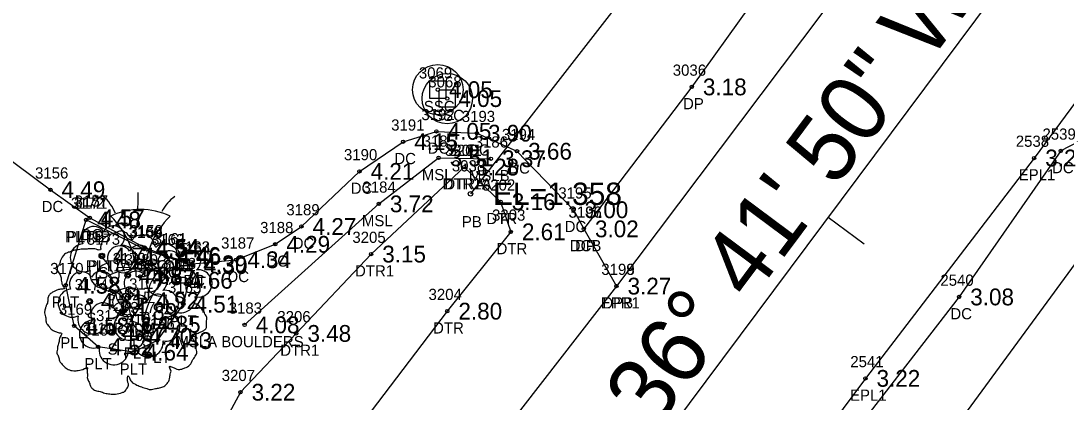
# Model space of a CAD drawing. Extents: x 2608598 to 2610682, y 641451 to 643526.
# Drawn here: x 2609967.6 to 2610061, y 642037.2 to 642071.3 of the extents above; entities that cross this region are included whole.
import ezdxf

# ---------------------------------------------------------------- set-up
doc = ezdxf.new("R2010")
doc.units = 0
for name, color, linetype in [('RD_EX_BldgApp', 7, 'Continuous'), ('RD_EX_BldgApp_txCode', 7, 'Continuous'), ('RD_EX_Conc', 7, 'Continuous'), ('RD_EX_Conc_txCode', 7, 'Continuous'), ('RD_EX_DR_Pipe', 7, 'Continuous'), ('RD_EX_DR_Pipe_txCode', 7, 'Continuous'), ('RD_EX_Driveway', 7, 'Continuous'), ('RD_EX_Driveway_txCode', 7, 'Continuous'), ('RD_EX_H2O', 7, 'Continuous'), ('RD_EX_H2O_txCode', 7, 'Continuous'), ('RD_EX_Misc', 7, 'Continuous'), ('RD_EX_Misc_txCode', 7, 'Continuous'), ('RD_EX_Road', 7, 'Continuous'), ('RD_EX_Road_txCode', 7, 'Continuous'), ('RD_EX_TX_BldgApp_ELEV', 7, 'Continuous'), ('RD_EX_TX_Conc_ELEV', 7, 'Continuous'), ('RD_EX_TX_Driveway_ELEV', 7, 'Continuous'), ('RD_EX_TX_H2O_ELEV', 7, 'Continuous'), ('RD_EX_TX_Misc_ELEV', 7, 'Continuous'), ('RD_EX_TX_Road_ELEV', 7, 'Continuous'), ('RD_EX_TX_UT_ELEV', 7, 'Continuous'), ('RD_EX_TX_VEG_ELEV', 7, 'Continuous'), ('RD_EX_UT', 7, 'Continuous'), ('RD_EX_UT_txCode', 7, 'Continuous'), ('RD_EX_VEG', 7, 'Continuous'), ('RD_EX_VEG_txCode', 7, 'Continuous'), ('RD_HC_Cl', 7, 'Continuous'), ('RD_HC_Data', 7, 'Continuous'), ('RD_HC_Data_Tic', 7, 'Continuous'), ('RD_SMD_Locator', 7, 'Continuous'), ('RD_TX_Pipe_ElevEX', 7, 'Continuous')]:
    doc.layers.add(name, color=color, linetype=linetype)

msp = doc.modelspace()

# ---------------------------------------------------------------- linework, layer by layer
at = {"layer": 'RD_EX_BldgApp'}
for p, q in [((2609978.641, 642050.937), (2609973.438, 642053.541)), ((2609977.922, 642048.486), (2609978.672, 642048.486)), ((2609977.679, 642043.16), (2609978.429, 642043.16))]:
    msp.add_line(p, q, dxfattribs=at)
msp.add_lwpolyline([(2609978.641, 642050.937), (2609980.61, 642050.282), (2609982.959, 642049.455), (2609982.128, 642046.005), (2609979.78, 642042.749), (2609977.686, 642041.715), (2609974.532, 642042.189), (2609972.382, 642044.057), (2609971.623, 642047.695), (2609973.438, 642053.541)], dxfattribs=at)
for centre, radius, start, end in [((2609971.605, 642052.128), 4.895, 24.32791, 46.26654), ((2609940.216, 642055.824), 37.876, 358.06712, 0.27154), ((2609983.185, 642052.879), 3.283, 123.29064, 154.48862), ((2609978.297, 642048.486), 5.997, 63.77943, 116.22057), ((2609970.422, 642048.486), 7.5, 0, 45.83662), ((2609986.172, 642048.486), 7.5, 134.16338, 180), ((2609971.361, 642046.803), 4.895, 24.32791, 46.26654), ((2609939.972, 642050.498), 37.876, 358.06712, 0.27154), ((2609982.942, 642047.553), 3.283, 123.29064, 154.48862), ((2609978.054, 642043.16), 5.997, 63.77943, 116.22057), ((2609970.179, 642043.16), 7.5, 0, 45.83662), ((2609985.929, 642043.16), 7.5, 134.16338, 180)]:
    msp.add_arc(centre, radius, start, end, dxfattribs=at)
at = {"layer": 'RD_EX_Conc'}
for points in [[(2609961.016, 642063.114), (2609970.253, 642056.24), (2609973.77, 642053.725), (2609978.671, 642051.077), (2609980.569, 642050.362), (2609982.905, 642049.619), (2609986.846, 642049.978), (2609990.334, 642051.359), (2609992.677, 642052.953), (2609997.86, 642057.875), (2610001.755, 642060.528), (2610004.736, 642061.459), (2610008.347, 642061.293), (2610011.93, 642059.679), (2610016.967, 642054.45), (2610017.895, 642052.738)], [(2610062.865, 642060.944), (2610060.494, 642059.714), (2610051.415, 642046.652), (2610037.455, 642028.596), (2610032.589, 642022.148), (2610033.33, 642021.486)]]:
    msp.add_lwpolyline(points, dxfattribs=at)
at = {"layer": 'RD_EX_DR_Pipe'}
for p, q in [((2610033.217, 642088.618), (2610007.781, 642055.878)), ((2610073.519, 642065.711), (2609997.656, 641962.025))]:
    msp.add_line(p, q, dxfattribs=at)
at = {"layer": 'RD_EX_Driveway'}
msp.add_lwpolyline([(2610042.94, 642077.419), (2610037.979, 642080.001), (2610027.537, 642065.432), (2610017.895, 642052.738), (2610020.807, 642047.622)], dxfattribs=at)
at = {"layer": 'RD_EX_H2O'}
for points in [[(2610007.204, 642058.263), (2609998.896, 642050.485), (2609992.217, 642043.39), (2609987.228, 642038.134), (2609984.424, 642032.942), (2609982.751, 642025.12), (2609982.447, 642024.16), (2609981.196, 642022.387), (2609981.259, 642019.853), (2609982.724, 642019.295), (2609985.043, 642018.208), (2609987.753, 642019.505)], [(2610007.204, 642058.263), (2610010.468, 642055.164), (2610011.37, 642052.471), (2610005.7, 642045.381), (2609992.131, 642027.498), (2609987.753, 642019.505)]]:
    msp.add_lwpolyline(points, dxfattribs=at)
at = {"layer": 'RD_EX_Misc'}
msp.add_lwpolyline([(2609987.6, 642044.154), (2609999.579, 642054.974), (2610004.928, 642059.092), (2610009.602, 642059.01)], dxfattribs=at)
at = {"layer": 'RD_EX_Road'}
for points in [[(2610073.957, 642143.053), (2610073.967, 642133.893), (2610072.62, 642129.267), (2610072.125, 642123.733), (2610071.192, 642117.593), (2610042.94, 642077.419), (2610042.982, 642077.082), (2610020.807, 642047.622), (2610010.682, 642034.572), (2609995.36, 642013.506), (2609993.975, 642012.164), (2609992.649, 642010.593), (2609982.727, 641996.329), (2609971.725, 641982.02), (2609971.56, 641981.898), (2609965.999, 641974.618)], [(2610116.512, 642103.007), (2610109.419, 642106.335), (2610102.937, 642107.104), (2610095.974, 642105.732), (2610091.028, 642103.088), (2610067.446, 642071.713), (2610058.11, 642059.075), (2610043.044, 642039.371), (2610035.942, 642029.795), (2610030.832, 642022.851), (2609999.348, 641980.077), (2609984.87, 641960.622)]]:
    msp.add_lwpolyline(points, dxfattribs=at)
at = {"layer": 'RD_EX_UT'}
for p, q in [((2610005.61, 642065.935), (2610004.11, 642065.935)), ((2610004.11, 642065.935), (2610004.11, 642064.435)), ((2610005.61, 642064.435), (2610005.61, 642065.935)), ((2610006.449, 642065.138), (2610004.949, 642065.138)), ((2610004.949, 642065.138), (2610004.949, 642063.638)), ((2610006.449, 642063.638), (2610006.449, 642065.138)), ((2610004.11, 642064.435), (2610005.61, 642064.435)), ((2610004.949, 642063.638), (2610006.449, 642063.638))]:
    msp.add_line(p, q, dxfattribs=at)
for centre in [(2610004.86, 642065.185), (2610005.699, 642064.388)]:
    msp.add_circle(centre, 2.25, dxfattribs=at)
at = {"layer": 'RD_EX_VEG'}
for centre, radius in [((2609974.848, 642050.317), 0.25), ((2609977.162, 642048.587), 0.25), ((2609981.64, 642048.142), 0.25), ((2609973.771, 642046.254), 0.25), ((2609978.635, 642046.316), 0.25), ((2609976.68, 642045.355), 0.25), ((2609976.668, 642045.336), 0.0001), ((2609978.765, 642044.205), 0.25), ((2609975.675, 642043.494), 0.25)]:
    msp.add_circle(centre, radius, dxfattribs=at)
for centre, radius, start, end in [((2609974.127, 642051.864), 1.084, 34.97629, 204.75602), ((2609975.893, 642052.019), 0.995, 308.76261, 152.04674), ((2609973.284, 642050.162), 1.257, 96.45179, 294.73401), ((2609976.44, 642050.134), 1.084, 34.97629, 204.75602), ((2609976.687, 642050.038), 1.218, 256.56668, 98.10463), ((2609978.207, 642050.289), 0.995, 308.76261, 152.04674), ((2609980.919, 642049.69), 1.084, 34.97629, 204.75602), ((2609982.685, 642049.844), 0.995, 308.76261, 152.04674), ((2609973.05, 642047.801), 1.084, 34.97629, 204.75602), ((2609975.093, 642048.721), 1.318, 166.88266, 5.75893), ((2609974.816, 642047.956), 0.995, 308.76261, 152.04674), ((2609975.598, 642048.431), 1.257, 96.45179, 294.73401), ((2609977.914, 642047.863), 1.084, 34.97629, 204.75602), ((2609979.001, 642048.307), 1.218, 256.56668, 98.10463), ((2609979.68, 642048.018), 0.995, 308.76261, 152.04674), ((2609980.076, 642047.987), 1.257, 96.45179, 294.73401), ((2609983.48, 642047.863), 1.218, 256.56668, 98.10463), ((2609972.207, 642046.098), 1.257, 96.45179, 294.73401), ((2609975.611, 642045.974), 1.218, 256.56668, 98.10463), ((2609977.071, 642046.161), 1.257, 96.45179, 294.73401), ((2609977.407, 642046.99), 1.318, 166.88266, 5.75893), ((2609980.474, 642046.037), 1.218, 256.56668, 98.10463), ((2609974.954, 642045.041), 1.084, 34.97629, 204.75602), ((2609976.72, 642045.196), 0.995, 308.76261, 152.04674), ((2609978.044, 642045.752), 1.084, 34.97629, 204.75602), ((2609979.81, 642045.907), 0.995, 308.76261, 152.04674), ((2609981.886, 642046.546), 1.318, 166.88266, 5.75893), ((2609977.201, 642044.049), 1.257, 96.45179, 294.73401), ((2609980.604, 642043.926), 1.218, 256.56668, 98.10463), ((2609974.017, 642044.657), 1.318, 166.88266, 5.75893), ((2609974.111, 642043.338), 1.257, 96.45179, 294.73401), ((2609977.514, 642043.215), 1.218, 256.56668, 98.10463), ((2609978.88, 642044.72), 1.318, 166.88266, 5.75893), ((2609979.01, 642042.609), 1.318, 166.88266, 5.75893), ((2609975.92, 642041.898), 1.318, 166.88266, 5.75893)]:
    msp.add_arc(centre, radius, start, end, dxfattribs=at)
for points in [[(2609976.812, 642052.522), (2609976.512, 642052.547), (2609976.188, 642052.447), (2609975.938, 642052.347), (2609975.713, 642052.272), (2609975.488, 642052.172), (2609975.188, 642051.997), (2609974.963, 642051.797), (2609974.838, 642051.547), (2609974.788, 642051.323), (2609974.738, 642051.048), (2609974.738, 642050.873), (2609974.613, 642050.848), (2609974.463, 642050.873), (2609974.213, 642050.948), (2609973.963, 642050.948), (2609973.714, 642050.948), (2609973.364, 642050.923), (2609973.014, 642050.923), (2609972.739, 642050.873), (2609972.414, 642050.823), (2609972.039, 642050.698), (2609971.689, 642050.573), (2609971.39, 642050.323), (2609971.14, 642049.848), (2609971.015, 642049.498), (2609970.865, 642049.248), (2609971.015, 642048.799), (2609971.19, 642048.449), (2609971.215, 642048.249), (2609971.29, 642047.824), (2609971.39, 642047.599), (2609971.515, 642047.399), (2609971.44, 642047.374), (2609971.065, 642047.324), (2609970.765, 642047.224), (2609970.34, 642046.999), (2609970.115, 642046.775), (2609970.015, 642046.45), (2609969.99, 642046.1), (2609969.89, 642045.9), (2609969.815, 642045.625), (2609969.79, 642045.55), (2609969.74, 642045.225), (2609969.84, 642044.775), (2609969.865, 642044.426), (2609969.99, 642044.201), (2609970.14, 642044.026), (2609970.315, 642043.776), (2609970.715, 642043.551), (2609971.04, 642043.451), (2609971.24, 642043.426), (2609971.065, 642042.926), (2609971.015, 642042.576), (2609970.89, 642042.177), (2609970.89, 642042.102), (2609970.84, 642041.627), (2609970.99, 642041.302), (2609971.065, 642040.927), (2609971.24, 642040.702), (2609971.515, 642040.402), (2609971.839, 642040.177), (2609972.339, 642040.052), (2609972.739, 642040.077), (2609973.314, 642040.252), (2609973.564, 642040.327), (2609973.539, 642040.152), (2609973.564, 642039.778), (2609973.564, 642039.353), (2609973.714, 642039.028), (2609973.814, 642038.753), (2609973.963, 642038.503), (2609974.288, 642038.278), (2609974.688, 642038.203), (2609975.113, 642038.053), (2609975.563, 642037.978), (2609976.063, 642037.953), (2609976.662, 642038.103), (2609976.937, 642038.228), (2609977.037, 642038.403), (2609977.237, 642038.778), (2609977.187, 642039.003), (2609977.212, 642039.603), (2609977.312, 642039.428), (2609977.487, 642039.078), (2609977.987, 642038.778), (2609978.387, 642038.603), (2609978.861, 642038.453), (2609979.161, 642038.378), (2609979.636, 642038.453), (2609980.011, 642038.528), (2609980.386, 642038.653), (2609980.686, 642038.928), (2609980.86, 642039.203), (2609980.91, 642039.478), (2609980.985, 642039.853), (2609981.035, 642040.027)], [(2609981.035, 642040.027), (2609980.96, 642040.202), (2609980.91, 642040.452), (2609980.985, 642040.427), (2609981.16, 642040.377), (2609981.435, 642040.252), (2609981.66, 642040.177), (2609981.985, 642040.202), (2609982.26, 642040.302), (2609982.71, 642040.577), (2609982.985, 642041.052), (2609983.259, 642041.452), (2609983.334, 642041.777), (2609983.284, 642042.002), (2609983.259, 642042.501), (2609983.059, 642042.751), (2609983.009, 642042.876), (2609982.91, 642043.276), (2609982.985, 642043.326), (2609983.259, 642043.376), (2609983.634, 642043.501), (2609983.909, 642043.626), (2609984.134, 642043.801), (2609984.209, 642044.026), (2609984.184, 642044.426), (2609984.234, 642044.825), (2609984.159, 642044.975), (2609984.059, 642045.125), (2609983.984, 642045.325), (2609983.834, 642045.475), (2609983.734, 642045.625), (2609983.634, 642045.725), (2609983.509, 642045.875), (2609983.334, 642046), (2609983.184, 642046.05), (2609983.134, 642046.2), (2609983.284, 642046.4), (2609983.334, 642046.5), (2609983.359, 642046.725), (2609983.584, 642047.074), (2609983.634, 642047.474), (2609983.584, 642047.899), (2609983.534, 642048.174), (2609983.384, 642048.449), (2609983.184, 642048.699), (2609983.059, 642048.874), (2609982.885, 642048.999), (2609982.56, 642049.124), (2609982.31, 642049.173), (2609981.96, 642049.173), (2609981.76, 642049.223), (2609981.785, 642049.273), (2609981.785, 642049.423), (2609981.785, 642049.698), (2609981.71, 642050.148), (2609981.56, 642050.648), (2609981.56, 642050.673), (2609981.46, 642050.923), (2609981.235, 642051.123), (2609981.06, 642051.223), (2609980.86, 642051.348), (2609980.611, 642051.373), (2609980.311, 642051.373), (2609980.036, 642051.323), (2609979.836, 642051.223), (2609979.661, 642051.098), (2609979.586, 642051.248), (2609979.486, 642051.547), (2609979.436, 642051.697), (2609979.286, 642051.872), (2609979.061, 642052.072), (2609978.611, 642052.197), (2609977.987, 642052.122), (2609977.687, 642051.922), (2609977.537, 642051.747), (2609977.487, 642051.872), (2609977.287, 642052.072), (2609977.187, 642052.247), (2609977.012, 642052.372), (2609976.862, 642052.472), (2609976.762, 642052.522)]]:
    msp.add_spline(points, degree=3, dxfattribs=at)
at = {"layer": 'RD_HC_Cl'}
msp.add_line((2610099.475, 642133.968), (2609975.324, 641967.39), dxfattribs=at)
at = {"layer": 'RD_HC_Data_Tic'}
msp.add_line((2610039.716, 642053.788), (2610042.924, 642051.398), dxfattribs=at)
at = {"layer": 'RD_SMD_Locator'}
for centre, radius in [((2610004.86, 642065.185), 0.15), ((2610027.537, 642065.432), 0.15), ((2610005.699, 642064.388), 0.15), ((2610004.736, 642061.459), 0.15), ((2610008.347, 642061.293), 0.15), ((2610001.755, 642060.528), 0.15), ((2610004.928, 642059.092), 0.15), ((2610009.602, 642059.01), 0.15), ((2610011.93, 642059.679), 0.15), ((2610058.11, 642059.075), 0.15), ((2610060.494, 642059.714), 0.15), ((2610007.204, 642058.263), 0.15), ((2610007.204, 642058.263), 0.15), ((2609997.86, 642057.875), 0.15), ((2609970.253, 642056.24), 0.15), ((2610007.781, 642055.878), 0.2), ((2609999.579, 642054.974), 0.15), ((2610010.468, 642055.164), 0.15), ((2610016.967, 642054.45), 0.15), ((2609973.438, 642053.541), 0.15), ((2609973.438, 642053.541), 0.15), ((2609973.77, 642053.725), 0.15), ((2609992.677, 642052.953), 0.15), ((2610011.37, 642052.471), 0.15), ((2610017.895, 642052.738), 0.15), ((2610017.895, 642052.738), 0.15), ((2609978.641, 642050.937), 0.15), ((2609978.641, 642050.937), 0.15), ((2609978.671, 642051.077), 0.15), ((2609990.334, 642051.359), 0.15), ((2609974.848, 642050.317), 0.15), ((2609980.569, 642050.362), 0.15), ((2609980.61, 642050.282), 0.15), ((2609986.846, 642049.978), 0.15), ((2609998.896, 642050.485), 0.15), ((2609982.905, 642049.619), 0.15), ((2609982.959, 642049.455), 0.15), ((2609977.162, 642048.587), 0.15), ((2609978.269, 642048.468), 0.15), ((2609981.64, 642048.142), 0.15), ((2609971.623, 642047.695), 0.15), ((2610020.807, 642047.622), 0.15), ((2610020.807, 642047.622), 0.15), ((2609973.771, 642046.254), 0.15), ((2609978.635, 642046.316), 0.15), ((2609982.128, 642046.005), 0.15), ((2610051.415, 642046.652), 0.15), ((2609976.68, 642045.355), 0.15), ((2610005.7, 642045.381), 0.15), ((2609972.382, 642044.057), 0.15), ((2609978.765, 642044.205), 0.15), ((2609987.6, 642044.154), 0.15), ((2609975.675, 642043.494), 0.15), ((2609978.026, 642043.142), 0.15), ((2609992.217, 642043.39), 0.15), ((2609974.532, 642042.189), 0.15), ((2609979.78, 642042.749), 0.15), ((2609977.686, 642041.715), 0.15), ((2610043.044, 642039.371), 0.15), ((2609987.228, 642038.134), 0.15)]:
    msp.add_circle(centre, radius, dxfattribs=at)

# ---------------------------------------------------------------- texts
at = {"layer": 'RD_EX_BldgApp_txCode'}
for s, p in [('3172', (2609972.091, 642054.541)), ('3171', (2609972.375, 642054.541)), ('3160', (2609977.231, 642051.937)), ('3159', (2609977.294, 642051.937)), ('PLT1B', (2609971.556, 642051.541)), ('PLTB', (2609971.721, 642051.541)), ('3162', (2609979.24, 642051.282)), ('3164', (2609981.589, 642050.455)), ('PLT1A 4STONE', (2609973.416, 642048.937)), ('PLTA 4STONE', (2609973.582, 642048.937)), ('3180', (2609976.883, 642049.468)), ('3170', (2609970.237, 642048.695)), ('PLT', (2609979.366, 642048.282)), ('3165', (2609980.757, 642047.005)), ('PLT', (2609981.715, 642047.455)), ('FLT', (2609977.049, 642046.468)), ('PLT', (2609970.379, 642045.695)), ('3169', (2609971.012, 642045.057)), ('3181', (2609976.963, 642044.142)), ('3166', (2609978.387, 642043.749)), ('PLT', (2609980.883, 642044.005)), ('3168', (2609973.162, 642043.189)), ('3167', (2609976.315, 642042.715)), ('PLT', (2609971.138, 642042.057)), ('FLT', (2609976.806, 642041.142)), ('PLT', (2609978.536, 642040.749)), ('PLT', (2609973.288, 642040.189)), ('PLT', (2609976.441, 642039.715))]:
    msp.add_text(s, height=1, dxfattribs=at).set_placement(p)
at = {"layer": 'RD_EX_Conc_txCode'}
for s, p in [('3192', (2610003.39, 642062.459)), ('3193', (2610007.001, 642062.293)), ('3191', (2610000.692, 642061.528)), ('3194', (2610010.583, 642060.679)), ('2539', (2610058.864, 642060.714)), ('DC', (2610003.957, 642059.459)), ('DC', (2610007.568, 642059.293)), ('3190', (2609996.474, 642058.875)), ('DC', (2610000.976, 642058.528)), ('3156', (2609968.883, 642057.24)), ('DC', (2610011.15, 642057.679)), ('DC', (2610059.715, 642057.714)), ('DC', (2609997.081, 642055.875)), ('3195', (2610015.62, 642055.45)), ('3157', (2609972.424, 642054.725)), ('DC', (2609969.473, 642054.24)), ('3189', (2609991.331, 642053.953)), ('3196', (2610016.525, 642053.738)), ('DC', (2609972.99, 642051.725)), ('3158', (2609977.324, 642052.077)), ('3188', (2609988.987, 642052.359)), ('DC', (2610016.187, 642052.45)), ('3161', (2609979.482, 642051.362)), ('3187', (2609985.5, 642050.978)), ('DC', (2609991.898, 642050.953)), ('DCB', (2610016.643, 642050.738)), ('3163', (2609981.535, 642050.619)), ('DC', (2609977.891, 642049.077)), ('DC', (2609989.554, 642049.359)), ('DC', (2609979.789, 642048.362)), ('DC', (2609986.067, 642047.978)), ('DC', (2609982.125, 642047.619)), ('2540', (2610049.746, 642047.652)), ('DC', (2610050.635, 642044.652))]:
    msp.add_text(s, height=1, dxfattribs=at).set_placement(p)
at = {"layer": 'RD_EX_DR_Pipe_txCode'}
for s, p in [('3038', (2610006.112, 642057.878)), ('PB', (2610007.001, 642052.878))]:
    msp.add_text(s, height=1, dxfattribs=at).set_placement(p)
at = {"layer": 'RD_EX_Driveway_txCode'}
for s, p in [('3036', (2610025.844, 642066.432)), ('DP', (2610026.757, 642063.432)), ('3197', (2610016.548, 642053.738)), ('DP', (2610017.115, 642050.738)), ('3198', (2610019.46, 642048.622)), ('DPB', (2610019.555, 642045.622))]:
    msp.add_text(s, height=1, dxfattribs=at).set_placement(p)
at = {"layer": 'RD_EX_H2O_txCode'}
for s, p in [('3200', (2610005.495, 642059.263)), ('3201', (2610005.818, 642059.263)), ('DTR1A', (2610005.282, 642056.263)), ('DTRA', (2610005.448, 642056.263)), ('3202', (2610008.799, 642056.164)), ('3203', (2610009.701, 642053.471)), ('DTR', (2610009.2, 642053.164)), ('3205', (2609997.227, 642051.485)), ('DTR', (2610010.102, 642050.471)), ('DTR1', (2609997.463, 642048.485)), ('3204', (2610004.03, 642046.381)), ('3206', (2609990.524, 642044.39)), ('DTR', (2610004.432, 642043.381)), ('DTR1', (2609990.784, 642041.39)), ('3207', (2609985.558, 642039.134))]:
    msp.add_text(s, height=1, dxfattribs=at).set_placement(p)
at = {"layer": 'RD_EX_Misc_txCode'}
for s, p in [('3185', (2610003.499, 642060.092)), ('3186', (2610008.153, 642060.01)), ('MSL', (2610003.426, 642057.092)), ('MSLB', (2610007.632, 642057.01)), ('3184', (2609998.127, 642055.974)), ('MSL', (2609998.077, 642052.974)), ('3183', (2609986.184, 642045.154)), ('MSLA BOULDERS', (2609981.507, 642042.154))]:
    msp.add_text(s, height=1, dxfattribs=at).set_placement(p)
at = {"layer": 'RD_EX_Road_txCode'}
for s, p in [('2538', (2610056.48, 642060.075)), ('EPL1', (2610056.74, 642057.075)), ('3199', (2610019.46, 642048.622)), ('EPR1', (2610019.413, 642045.622)), ('2541', (2610041.697, 642040.371)), ('EPL1', (2610041.674, 642037.371))]:
    msp.add_text(s, height=1, dxfattribs=at).set_placement(p)
at = {"layer": 'RD_EX_TX_BldgApp_ELEV'}
for s, p in [('4.48', (2609974.438, 642052.791)), ('4.48', (2609974.438, 642052.791)), ('4.54', (2609979.641, 642050.187)), ('4.54', (2609979.641, 642050.187)), ('4.46', (2609981.61, 642049.532)), ('4.30', (2609983.959, 642048.705)), ('4.82', (2609979.269, 642047.718)), ('4.58', (2609972.623, 642046.945)), ('4.51', (2609983.128, 642045.255)), ('4.58', (2609973.382, 642043.307)), ('4.70', (2609979.026, 642042.392)), ('4.43', (2609980.78, 642041.999)), ('4.52', (2609975.532, 642041.439)), ('4.64', (2609978.686, 642040.965))]:
    msp.add_text(s, height=1.5, dxfattribs=at).set_placement(p)
at = {"layer": 'RD_EX_TX_Conc_ELEV'}
for s, p in [('4.05', (2610005.736, 642060.709)), ('3.90', (2610009.347, 642060.543)), ('4.15', (2610002.755, 642059.778)), ('3.66', (2610012.93, 642058.929)), ('4.21', (2609998.86, 642057.125)), ('4.49', (2609971.253, 642055.49)), ('4.57', (2609974.77, 642052.975)), ('3.00', (2610017.967, 642053.7)), ('4.27', (2609993.677, 642052.203)), ('3.02', (2610018.895, 642051.988)), ('4.54', (2609979.671, 642050.327)), ('4.29', (2609991.334, 642050.609)), ('4.46', (2609981.569, 642049.612)), ('4.34', (2609987.846, 642049.228)), ('4.39', (2609983.905, 642048.869)), ('3.08', (2610052.415, 642045.902))]:
    msp.add_text(s, height=1.5, dxfattribs=at).set_placement(p)
at = {"layer": 'RD_EX_TX_Driveway_ELEV'}
for s, p in [('3.18', (2610028.537, 642064.682)), ('3.02', (2610018.895, 642051.988)), ('3.27', (2610021.807, 642046.872))]:
    msp.add_text(s, height=1.5, dxfattribs=at).set_placement(p)
at = {"layer": 'RD_EX_TX_H2O_ELEV'}
for s, p in [('3.28', (2610008.204, 642057.513)), ('3.28', (2610008.204, 642057.513)), ('3.16', (2610011.468, 642054.414)), ('2.61', (2610012.37, 642051.721)), ('3.15', (2609999.896, 642049.735)), ('2.80', (2610006.7, 642044.631)), ('3.48', (2609993.217, 642042.64)), ('3.22', (2609988.228, 642037.384))]:
    msp.add_text(s, height=1.5, dxfattribs=at).set_placement(p)
at = {"layer": 'RD_EX_TX_Misc_ELEV'}
for s, p in [('3.51', (2610005.928, 642058.342)), ('3.37', (2610010.602, 642058.26)), ('3.72', (2610000.579, 642054.224)), ('4.08', (2609988.6, 642043.404))]:
    msp.add_text(s, height=1.5, dxfattribs=at).set_placement(p)
at = {"layer": 'RD_EX_TX_Road_ELEV'}
for s, p in [('3.20', (2610059.11, 642058.325)), ('3.27', (2610021.807, 642046.872)), ('3.22', (2610044.044, 642038.621))]:
    msp.add_text(s, height=1.5, dxfattribs=at).set_placement(p)
at = {"layer": 'RD_EX_TX_UT_ELEV'}
for p in [(2610005.86, 642064.435), (2610006.699, 642063.638)]:
    msp.add_text('4.05', height=1.5, dxfattribs=at).set_placement(p)
at = {"layer": 'RD_EX_TX_VEG_ELEV'}
for s, p in [('4.71', (2609975.848, 642049.567)), ('4.88', (2609978.162, 642047.837)), ('4.66', (2609982.64, 642047.392)), ('4.81', (2609974.771, 642045.504)), ('4.92', (2609979.635, 642045.566)), ('4.89', (2609977.68, 642044.605)), ('4.87', (2609976.675, 642042.744)), ('4.85', (2609979.765, 642043.455))]:
    msp.add_text(s, height=1.5, dxfattribs=at).set_placement(p)
at = {"layer": 'RD_EX_UT_txCode'}
for s, p in [('3069', (2610003.167, 642066.185)), ('3068', (2610004.006, 642065.388)), ('SSC', (2610003.608, 642063.185)), ('SSC', (2610004.447, 642062.388))]:
    msp.add_text(s, height=1, dxfattribs=at).set_placement(p)
at = {"layer": 'RD_EX_VEG_txCode'}
for s, p in [('3173', (2609973.501, 642051.317)), ('3179', (2609975.815, 642049.587)), ('3178', (2609980.294, 642049.142)), ('S', (2609974.541, 642048.317)), ('3174', (2609972.425, 642047.254)), ('3177', (2609977.288, 642047.316)), ('3182', (2609975.334, 642046.355)), ('S', (2609976.854, 642046.587)), ('S', (2609981.333, 642046.142)), ('3176', (2609977.395, 642045.205)), ('S', (2609973.464, 642044.254)), ('3175', (2609974.328, 642044.494)), ('S', (2609978.328, 642044.316)), ('T 10PALM', (2609973.271, 642043.355)), ('S', (2609975.368, 642041.494)), ('S', (2609978.458, 642042.205))]:
    msp.add_text(s, height=1, dxfattribs=at).set_placement(p)
at = {"layer": 'RD_HC_Data'}
msp.add_text('S 36%%d 41\' 50" W', height=6, rotation=53.30287, dxfattribs=at).set_placement((2610019.672, 642028.568))
at = {"layer": 'RD_TX_Pipe_ElevEX'}
msp.add_text('EL=1.358', height=2, dxfattribs=at).set_placement((2610009.781, 642054.878))

doc.saveas('drawing.dxf')
